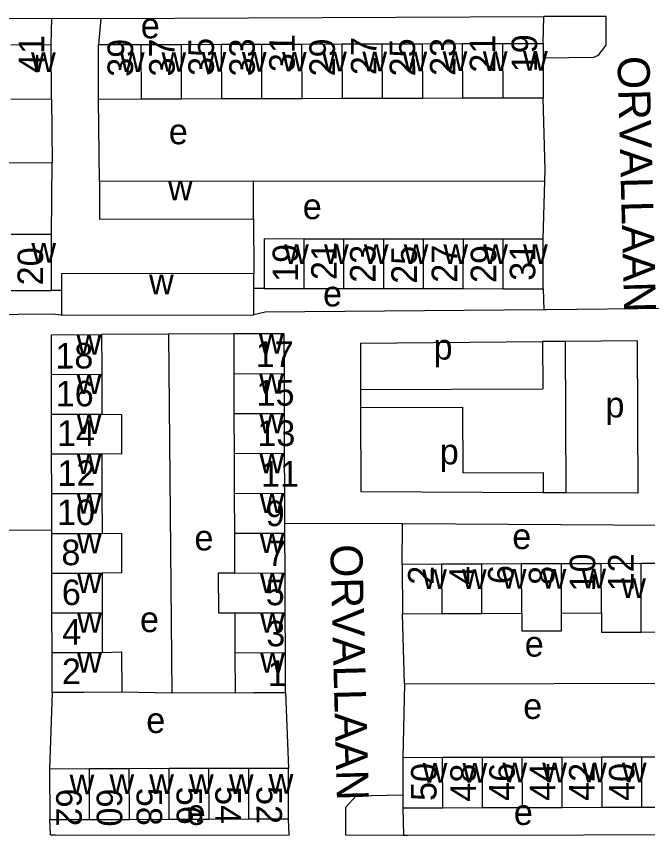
# Model space of a CAD drawing. Extents: x 159675 to 162108, y 386471 to 388472.
# Drawn here: x 161600.3 to 161699.1, y 388088 to 388216.2 of the extents above; entities that cross this region are included whole.
import ezdxf

# ---------------------------------------------------------------- set-up
doc = ezdxf.new("R2010")
doc.units = 0
for name, color, linetype in [('BLT_Basislijn', 7, 'Continuous'), ('BLT_Bebouwing', 7, 'Continuous'), ('BLT_Centroide', 7, 'Continuous'), ('BLT_Huisnummer', 7, 'Continuous'), ('BLT_Huisnummer_ tussenligend', 7, 'Continuous'), ('BLT_Onderverdeling_panden', 7, 'Continuous'), ('BLT_Straatnaam', 7, 'Continuous')]:
    doc.layers.add(name, color=color, linetype=linetype)

msp = doc.modelspace()

# ---------------------------------------------------------------- linework, layer by layer
at = {"layer": 'BLT_Basislijn'}
for p, q in [((161613.48, 388215.85), (161682.82, 388216.18)), ((161682.68, 388211.97), (161682.82, 388216.18)), ((161567.87, 388215.79), (161605.81, 388215.9)), ((161605.72, 388211.74), (161605.81, 388215.9)), ((161605.81, 388215.9), (161613.48, 388215.85)), ((161613.48, 388215.85), (161613.09, 388211.78)), ((161605.75, 388203.28), (161605.87, 388193.33)), ((161613.26, 388190.36), (161613.11, 388203.22)), ((161567.94, 388193.05), (161605.87, 388193.33)), ((161605.77, 388182.07), (161605.87, 388193.33)), ((161637.38, 388190.4), (161682.96, 388190.49)), ((161682.68, 388181.35), (161682.96, 388190.49)), ((161637.39, 388184.54), (161637.4, 388175.99)), ((161607.32, 388173.33), (161605.78, 388173.31)), ((161639.06, 388173.61), (161637.41, 388173.6)), ((161682.68, 388173.59), (161682.81, 388170.31)), ((161624.05, 388166.46), (161613.61, 388166.41)), ((161634.27, 388166.52), (161624.05, 388166.46)), ((161624.05, 388166.46), (161624.6, 388110.29)), ((161654.1, 388165.05), (161682.62, 388165.31)), ((161654.1, 388165.05), (161654.12, 388157.82)), ((161686.17, 388165.34), (161682.62, 388165.31)), ((161682.62, 388165.31), (161682.65, 388157.92)), ((161697.44, 388165.44), (161686.17, 388165.34)), ((161686.17, 388165.34), (161686.25, 388141.65)), ((161697.44, 388165.44), (161697.51, 388141.59)), ((161654.12, 388157.82), (161682.65, 388157.92)), ((161654.12, 388157.82), (161654.13, 388155.01)), ((161654.13, 388155.01), (161670.1, 388155.06)), ((161654.13, 388155.01), (161654.17, 388141.81)), ((161670.1, 388155.06), (161670.13, 388144.78)), ((161670.13, 388144.78), (161682.69, 388144.82)), ((161682.69, 388144.82), (161682.7, 388141.67)), ((161682.7, 388141.67), (161654.17, 388141.81)), ((161686.25, 388141.65), (161682.7, 388141.67)), ((161697.51, 388141.59), (161686.25, 388141.65)), ((161660.67, 388136.78), (161642.29, 388136.84)), ((161660.64, 388130.45), (161660.67, 388136.78)), ((161710.39, 388136.52), (161660.67, 388136.78)), ((161586.4, 388135.88), (161605.8, 388135.8)), ((161660.99, 388111.77), (161660.67, 388122.74)), ((161660.99, 388111.77), (161660.72, 388100.19)), ((161605.85, 388110.42), (161605.46, 388098.43)), ((161624.6, 388110.29), (161616.76, 388110.44)), ((161634.49, 388110.38), (161624.6, 388110.29)), ((161642.39, 388110.41), (161642.85, 388098.54)), ((161660.74, 388092.35), (161660.87, 388088.02)), ((161605.6, 388088.11), (161605.49, 388090.52)), ((161642.94, 388088.08), (161642.87, 388090.64))]:
    msp.add_line(p, q, dxfattribs=at)
for points in [[(161682.69, 388209.7), (161690.63, 388209.82), (161691.35, 388210.11), (161692.54, 388211.71), (161692.55, 388216.2), (161682.82, 388216.18)], [(161682.96, 388190.49), (161683.01, 388192.17), (161682.71, 388203.41)], [(161682.81, 388170.31), (161639.2, 388169.92), (161637.42, 388169.5)], [(161702.28, 388170.49), (161683.22, 388170.31), (161682.81, 388170.31)], [(161607.33, 388169.45), (161605.92, 388169.6), (161568.12, 388169.25)], [(161660.99, 388111.77), (161707.75, 388111.89), (161716.99, 388111.68)], [(161660.87, 388088.02), (161651.83, 388088.06), (161651.8, 388092.44), (161653.46, 388094.24), (161660.74, 388094.39)], [(161605.6, 388088.11), (161606.35, 388088.11), (161642.94, 388088.08)], [(161716.63, 388088.15), (161661.46, 388088.01), (161660.87, 388088.02)]]:
    msp.add_lwpolyline(points, dxfattribs=at)
at = {"layer": 'BLT_Bebouwing'}
for p, q in [((161605.72, 388211.74), (161599.37, 388211.72)), ((161605.75, 388203.28), (161605.72, 388211.74)), ((161613.09, 388211.78), (161619.81, 388211.8)), ((161613.11, 388203.22), (161613.09, 388211.78)), ((161619.81, 388211.8), (161626.09, 388211.82)), ((161626.09, 388211.82), (161632.38, 388211.83)), ((161632.38, 388211.83), (161638.67, 388211.85)), ((161638.67, 388211.85), (161644.95, 388211.87)), ((161644.95, 388211.87), (161651.24, 388211.89)), ((161651.24, 388211.89), (161657.52, 388211.9)), ((161657.52, 388211.9), (161663.81, 388211.92)), ((161663.81, 388211.92), (161670.1, 388211.94)), ((161670.1, 388211.94), (161676.38, 388211.95)), ((161676.38, 388211.95), (161682.68, 388211.97)), ((161682.68, 388211.97), (161682.69, 388209.7)), ((161682.69, 388209.7), (161682.71, 388203.41)), ((161599.39, 388203.26), (161605.75, 388203.28)), ((161626.13, 388203.26), (161619.85, 388203.24)), ((161632.42, 388203.28), (161626.13, 388203.26)), ((161638.7, 388203.29), (161632.42, 388203.28)), ((161644.99, 388203.31), (161638.7, 388203.29)), ((161651.28, 388203.33), (161644.99, 388203.31)), ((161657.56, 388203.35), (161651.28, 388203.33)), ((161663.85, 388203.36), (161657.56, 388203.35)), ((161670.13, 388203.38), (161663.85, 388203.36)), ((161676.42, 388203.4), (161670.13, 388203.38)), ((161682.71, 388203.41), (161676.42, 388203.4)), ((161619.85, 388203.24), (161613.11, 388203.22)), ((161637.38, 388190.4), (161613.26, 388190.36)), ((161637.39, 388184.54), (161637.38, 388190.4)), ((161605.77, 388182.07), (161599.43, 388182.06)), ((161605.78, 388173.31), (161605.77, 388182.07)), ((161651.52, 388181.36), (161645.29, 388181.36)), ((161657.75, 388181.36), (161651.52, 388181.36)), ((161663.99, 388181.36), (161657.75, 388181.36)), ((161670.22, 388181.35), (161663.99, 388181.36)), ((161676.45, 388181.35), (161670.22, 388181.35)), ((161682.68, 388181.35), (161676.45, 388181.35)), ((161682.68, 388173.59), (161682.68, 388181.35)), ((161637.41, 388173.6), (161637.4, 388175.99)), ((161599.44, 388173.3), (161605.78, 388173.31)), ((161607.32, 388173.33), (161607.33, 388169.45)), ((161637.42, 388169.5), (161637.41, 388173.6)), ((161639.06, 388173.61), (161645.29, 388173.61)), ((161645.29, 388173.61), (161651.52, 388173.6)), ((161651.52, 388173.6), (161657.75, 388173.6)), ((161657.75, 388173.6), (161663.98, 388173.6)), ((161663.98, 388173.6), (161670.21, 388173.6)), ((161670.21, 388173.6), (161676.45, 388173.59)), ((161676.45, 388173.59), (161682.68, 388173.59)), ((161607.33, 388169.45), (161637.42, 388169.5)), ((161613.61, 388166.41), (161613.61, 388166.1)), ((161634.27, 388166.52), (161634.27, 388166.33)), ((161605.77, 388153.96), (161605.76, 388160.17)), ((161613.62, 388160.2), (161613.63, 388153.97)), ((161634.29, 388160.28), (161634.32, 388154.05)), ((161642.22, 388154.08), (161642.2, 388160.31)), ((161605.78, 388147.74), (161605.77, 388153.96)), ((161634.32, 388154.05), (161634.34, 388147.81)), ((161642.24, 388147.84), (161642.22, 388154.08)), ((161605.79, 388141.52), (161605.78, 388147.74)), ((161613.65, 388147.75), (161613.66, 388141.53)), ((161634.34, 388147.81), (161634.37, 388141.57)), ((161642.27, 388141.6), (161642.24, 388147.84)), ((161605.8, 388135.8), (161605.79, 388141.52)), ((161613.66, 388141.53), (161613.67, 388135.31)), ((161634.37, 388141.57), (161634.39, 388135.33)), ((161642.29, 388136.84), (161642.27, 388141.6)), ((161642.29, 388135.36), (161642.29, 388136.84)), ((161605.81, 388135.3), (161605.8, 388135.8)), ((161634.39, 388135.33), (161634.41, 388129.1)), ((161642.32, 388129.13), (161642.29, 388135.36)), ((161605.82, 388129.08), (161605.81, 388135.3)), ((161666.87, 388130.47), (161660.64, 388130.45)), ((161660.64, 388130.45), (161660.67, 388122.74)), ((161673.1, 388130.49), (161666.87, 388130.47)), ((161679.33, 388130.52), (161673.1, 388130.49)), ((161685.56, 388130.54), (161679.33, 388130.52)), ((161691.79, 388130.56), (161685.56, 388130.54)), ((161698.02, 388130.58), (161691.79, 388130.56)), ((161704.25, 388130.6), (161698.02, 388130.58)), ((161605.83, 388122.86), (161605.82, 388129.08)), ((161613.68, 388129.09), (161613.69, 388122.88)), ((161642.34, 388122.89), (161642.32, 388129.13)), ((161605.84, 388116.64), (161605.83, 388122.86)), ((161613.69, 388122.88), (161613.7, 388116.66)), ((161634.44, 388122.86), (161634.46, 388116.62)), ((161642.36, 388116.65), (161642.34, 388122.89)), ((161660.67, 388122.74), (161666.9, 388122.76)), ((161666.9, 388122.76), (161673.13, 388122.78)), ((161673.13, 388122.78), (161679.36, 388122.8)), ((161685.59, 388122.83), (161691.82, 388122.85)), ((161605.85, 388110.42), (161605.84, 388116.64)), ((161634.46, 388116.62), (161634.49, 388110.38)), ((161642.39, 388110.41), (161642.36, 388116.65)), ((161666.96, 388100.21), (161660.72, 388100.19)), ((161660.72, 388100.19), (161660.74, 388094.39)), ((161673.19, 388100.23), (161666.96, 388100.21)), ((161679.43, 388100.24), (161673.19, 388100.23)), ((161685.66, 388100.26), (161679.43, 388100.24)), ((161691.9, 388100.28), (161685.66, 388100.26)), ((161698.13, 388100.3), (161691.9, 388100.28)), ((161704.37, 388100.31), (161698.13, 388100.3)), ((161611.69, 388098.45), (161605.46, 388098.43)), ((161605.46, 388098.43), (161605.49, 388090.52)), ((161617.93, 388098.47), (161611.69, 388098.45)), ((161624.16, 388098.49), (161617.93, 388098.47)), ((161630.39, 388098.51), (161624.16, 388098.49)), ((161636.62, 388098.52), (161630.39, 388098.51)), ((161642.85, 388098.54), (161636.62, 388098.52)), ((161642.87, 388090.64), (161642.85, 388098.54)), ((161660.74, 388094.39), (161660.74, 388092.35)), ((161660.74, 388092.35), (161666.98, 388092.37)), ((161666.98, 388092.37), (161673.21, 388092.39)), ((161673.21, 388092.39), (161679.45, 388092.41)), ((161679.45, 388092.41), (161685.68, 388092.42)), ((161685.68, 388092.42), (161691.92, 388092.44)), ((161691.92, 388092.44), (161698.15, 388092.46)), ((161698.15, 388092.46), (161704.39, 388092.48)), ((161605.49, 388090.52), (161611.72, 388090.54)), ((161611.72, 388090.54), (161617.95, 388090.56)), ((161617.95, 388090.56), (161624.18, 388090.58)), ((161624.18, 388090.58), (161630.41, 388090.6)), ((161630.41, 388090.6), (161636.64, 388090.62)), ((161636.64, 388090.62), (161642.87, 388090.64))]:
    msp.add_line(p, q, dxfattribs=at)
for points in [[(161613.26, 388190.36), (161613.27, 388184.49), (161637.39, 388184.54)], [(161645.29, 388181.36), (161639.06, 388181.37), (161639.06, 388173.61)], [(161637.4, 388175.99), (161607.32, 388175.94), (161607.32, 388173.33)], [(161605.76, 388160.17), (161605.75, 388166.39), (161613.61, 388166.41)], [(161613.61, 388166.1), (161613.62, 388161.41), (161613.62, 388160.2)], [(161642.2, 388160.31), (161642.17, 388166.55), (161634.27, 388166.52)], [(161634.27, 388166.33), (161634.29, 388161.52), (161634.29, 388160.28)], [(161613.63, 388153.97), (161616.71, 388153.91), (161616.72, 388147.72), (161613.65, 388147.75)], [(161613.67, 388135.31), (161616.73, 388135.33), (161616.74, 388129.14), (161613.68, 388129.09)], [(161634.41, 388129.1), (161631.84, 388129.08), (161631.9, 388122.86), (161634.44, 388122.86)], [(161679.36, 388122.8), (161679.36, 388120.07), (161685.55, 388120.07), (161685.59, 388122.83)], [(161691.82, 388122.85), (161691.83, 388119.85), (161698.06, 388119.87)], [(161698.06, 388119.87), (161704.13, 388119.89), (161704.28, 388122.89)], [(161613.7, 388116.66), (161616.74, 388116.75), (161616.76, 388110.44)], [(161616.76, 388110.44), (161610.85, 388110.43), (161605.85, 388110.42)], [(161634.49, 388110.38), (161637.39, 388110.4), (161642.39, 388110.41)]]:
    msp.add_lwpolyline(points, dxfattribs=at)
at = {"layer": 'BLT_Onderverdeling_panden'}
for p, q in [((161619.85, 388203.24), (161619.81, 388211.8)), ((161626.13, 388203.26), (161626.09, 388211.82)), ((161632.42, 388203.28), (161632.38, 388211.83)), ((161638.7, 388203.29), (161638.67, 388211.85)), ((161644.99, 388203.31), (161644.95, 388211.87)), ((161651.28, 388203.33), (161651.24, 388211.89)), ((161657.56, 388203.35), (161657.52, 388211.9)), ((161663.85, 388203.36), (161663.81, 388211.92)), ((161670.13, 388203.38), (161670.1, 388211.94)), ((161676.42, 388203.4), (161676.38, 388211.95)), ((161645.29, 388173.61), (161645.29, 388181.36)), ((161651.52, 388173.6), (161651.52, 388181.36)), ((161657.75, 388173.6), (161657.75, 388181.36)), ((161663.98, 388173.6), (161663.99, 388181.36)), ((161670.21, 388173.6), (161670.22, 388181.35)), ((161676.45, 388173.59), (161676.45, 388181.35)), ((161605.76, 388160.17), (161613.62, 388160.2)), ((161634.29, 388160.28), (161642.2, 388160.31)), ((161605.77, 388153.96), (161613.63, 388153.97)), ((161634.32, 388154.05), (161642.22, 388154.08)), ((161605.78, 388147.74), (161613.65, 388147.75)), ((161634.34, 388147.81), (161642.24, 388147.84)), ((161605.79, 388141.52), (161613.66, 388141.53)), ((161634.37, 388141.57), (161642.27, 388141.6)), ((161634.39, 388135.33), (161642.29, 388135.36)), ((161605.81, 388135.3), (161613.67, 388135.31)), ((161666.9, 388122.76), (161666.87, 388130.47)), ((161673.13, 388122.78), (161673.1, 388130.49)), ((161679.36, 388122.8), (161679.33, 388130.52)), ((161685.59, 388122.83), (161685.56, 388130.54)), ((161691.82, 388122.85), (161691.79, 388130.56)), ((161698.06, 388119.87), (161698.02, 388130.58)), ((161605.82, 388129.08), (161613.68, 388129.09)), ((161634.41, 388129.1), (161642.32, 388129.13)), ((161605.83, 388122.86), (161613.69, 388122.88)), ((161634.44, 388122.86), (161642.34, 388122.89)), ((161605.84, 388116.64), (161613.7, 388116.66)), ((161634.46, 388116.62), (161642.36, 388116.65)), ((161666.98, 388092.37), (161666.96, 388100.21)), ((161673.21, 388092.39), (161673.19, 388100.23)), ((161679.45, 388092.41), (161679.43, 388100.24)), ((161685.68, 388092.42), (161685.66, 388100.26)), ((161691.92, 388092.44), (161691.9, 388100.28)), ((161698.15, 388092.46), (161698.13, 388100.3)), ((161611.72, 388090.54), (161611.69, 388098.45)), ((161617.95, 388090.56), (161617.93, 388098.47)), ((161624.18, 388090.58), (161624.16, 388098.49)), ((161630.41, 388090.6), (161630.39, 388098.51)), ((161636.64, 388090.62), (161636.62, 388098.52))]:
    msp.add_line(p, q, dxfattribs=at)

# ---------------------------------------------------------------- texts
at = {"layer": 'BLT_Centroide'}
for s, p in [('e', (161619.73, 388212.77)), ('w', (161602.56, 388207.5)), ('w', (161616.47, 388207.5)), ('w', (161622.97, 388207.53)), ('w', (161629.25, 388207.55)), ('w', (161635.55, 388207.56)), ('w', (161641.83, 388207.58)), ('w', (161648.11, 388207.59)), ('w', (161654.41, 388207.62)), ('w', (161660.69, 388207.62)), ('w', (161666.97, 388207.66)), ('w', (161673.27, 388207.66)), ('w', (161679.55, 388207.69)), ('e', (161624.12, 388196.19)), ('w', (161623.99, 388187.44)), ('e', (161645.08, 388184.48)), ('w', (161602.61, 388177.69)), ('w', (161642.17, 388177.48)), ('w', (161648.41, 388177.48)), ('w', (161654.64, 388177.48)), ('w', (161660.88, 388177.47)), ('w', (161667.09, 388177.47)), ('w', (161673.33, 388177.47)), ('w', (161679.56, 388177.47)), ('w', (161621.03, 388172.72)), ('e', (161648.25, 388170.82)), ('w', (161609.69, 388163.28)), ('w', (161638.23, 388163.41)), ('p', (161665.55, 388162.5)), ('w', (161609.7, 388157.09)), ('w', (161638.26, 388157.19)), ('p', (161692.45, 388153.45)), ('w', (161609.71, 388150.84)), ('w', (161638.28, 388150.94)), ('p', (161666.52, 388146.1)), ('w', (161609.72, 388144.62)), ('w', (161638.3, 388144.72)), ('w', (161609.73, 388138.41)), ('w', (161638.33, 388138.47)), ('e', (161628.13, 388132.63)), ('e', (161677.87, 388132.85)), ('w', (161609.74, 388132.19)), ('w', (161638.35, 388132.22)), ('w', (161609.76, 388125.97)), ('w', (161638.38, 388126)), ('w', (161663.77, 388126.61)), ('w', (161670, 388126.62)), ('w', (161676.23, 388126.64)), ('w', (161682.47, 388126.67)), ('w', (161688.69, 388126.7)), ('w', (161694.92, 388125.2)), ('w', (161609.77, 388119.75)), ('e', (161619.61, 388119.86)), ('w', (161638.41, 388119.75)), ('e', (161679.82, 388116.02)), ('w', (161609.77, 388113.53)), ('w', (161638.42, 388113.53)), ('e', (161679.58, 388106.27)), ('e', (161620.59, 388104.07)), ('w', (161688.8, 388096.36)), ('w', (161695.03, 388096.36)), ('w', (161663.84, 388096.28)), ('w', (161670.08, 388096.3)), ('w', (161676.33, 388096.33)), ('w', (161682.56, 388096.33)), ('w', (161608.59, 388094.48)), ('w', (161614.83, 388094.52)), ('w', (161621.05, 388094.52)), ('w', (161627.28, 388094.55)), ('w', (161633.52, 388094.55)), ('w', (161639.75, 388094.58)), ('e', (161626.92, 388089.68)), ('e', (161678.11, 388089.68))]:
    msp.add_text(s, height=4, dxfattribs=at).set_placement(p)
at = {"layer": 'BLT_Huisnummer'}
for s, rotation, p in [('41', 89.8307, (161604.61, 388207.33)), ('39', 89.846, (161618.52, 388206.74)), ('35', 89.846, (161631.17, 388206.88)), ('31', 89.846, (161643.82, 388207.47)), ('27', 89.846, (161656.61, 388207)), ('23', 89.846, (161668.98, 388206.88)), ('19', 89.846, (161681.75, 388207.45)), ('19', 89.9778, (161644.36, 388174.66)), ('23', 89.9778, (161656.47, 388174.52)), ('27', 89.9778, (161669.25, 388174.52)), ('31', 89.9778, (161681.48, 388174.83)), ('20', 89.9149, (161604.44, 388174.11)), ('18', 0.1031, (161606.36, 388161.1)), ('17', 0.2178, (161637.71, 388161.33)), ('14', 0.1031, (161606.62, 388148.98)), ('13', 0.2178, (161637.98, 388148.96)), ('10', 0.1031, (161606.61, 388136.6)), ('9', 0.2178, (161639.28, 388136.44)), ('10', 89.7994, (161690.84, 388126.2)), ('2', 89.7994, (161665.55, 388127.25)), ('6', 89.7994, (161678.06, 388127.37)), ('6', 0.1031, (161607.38, 388124.08)), ('5', 0.2178, (161639.29, 388124.06)), ('2', 0.1031, (161607.39, 388111.71)), ('1', 0.2178, (161639.6, 388111.41)), ('50', 89.8392, (161666.01, 388093.43)), ('46', 89.8392, (161678.24, 388093.44)), ('42', 89.8392, (161690.74, 388093.44)), ('62', 270.1739, (161606.48, 388095.38)), ('56', 270.1739, (161625.32, 388095.66)), ('52', 270.1739, (161637.83, 388095.77))]:
    msp.add_text(s, height=4, rotation=rotation, dxfattribs=at).set_placement(p)
at = {"layer": 'BLT_Huisnummer_ tussenligend'}
for s, rotation, p in [('37', 90.2542, (161625.05, 388206.8)), ('33', 90.2542, (161637.59, 388206.82)), ('29', 90.2542, (161650.13, 388206.81)), ('25', 90.2542, (161662.68, 388206.82)), ('21', 90.2542, (161675.22, 388207.4)), ('21', 89.9704, (161650.4, 388174.94)), ('25', 89.9704, (161662.94, 388174.36)), ('29', 89.9704, (161675.36, 388174.48)), ('16', 0.1021, (161606.42, 388155.17)), ('15', 0.2175, (161637.85, 388155.28)), ('12', 0.1021, (161606.69, 388142.74)), ('11', 0.2175, (161638.56, 388142.6)), ('8', 0.1021, (161607.31, 388130.32)), ('7', 0.2175, (161639.5, 388130.18)), ('12', 90.1932, (161696.88, 388126.24)), ('4', 90.1932, (161672.05, 388127.24)), ('8', 90.1932, (161684.46, 388127.24)), ('4', 0.1021, (161607.43, 388117.9)), ('3', 0.2175, (161639.38, 388117.62)), ('48', 90.1609, (161672.18, 388093.33)), ('44', 90.1609, (161684.6, 388093.45)), ('40', 90.1609, (161697.01, 388093.45)), ('60', 270.1739, (161612.82, 388095.37)), ('58', 270.1739, (161619.06, 388095.49)), ('54', 270.1739, (161631.39, 388095.76))]:
    msp.add_text(s, height=4, rotation=rotation, dxfattribs=at).set_placement(p)
at = {"layer": 'BLT_Straatnaam'}
for p in [(161694.33, 388209.94), (161649.38, 388133.55)]:
    msp.add_text('ORVALLAAN', height=5, rotation=271.5081, dxfattribs=at).set_placement(p)

doc.saveas('drawing.dxf')
